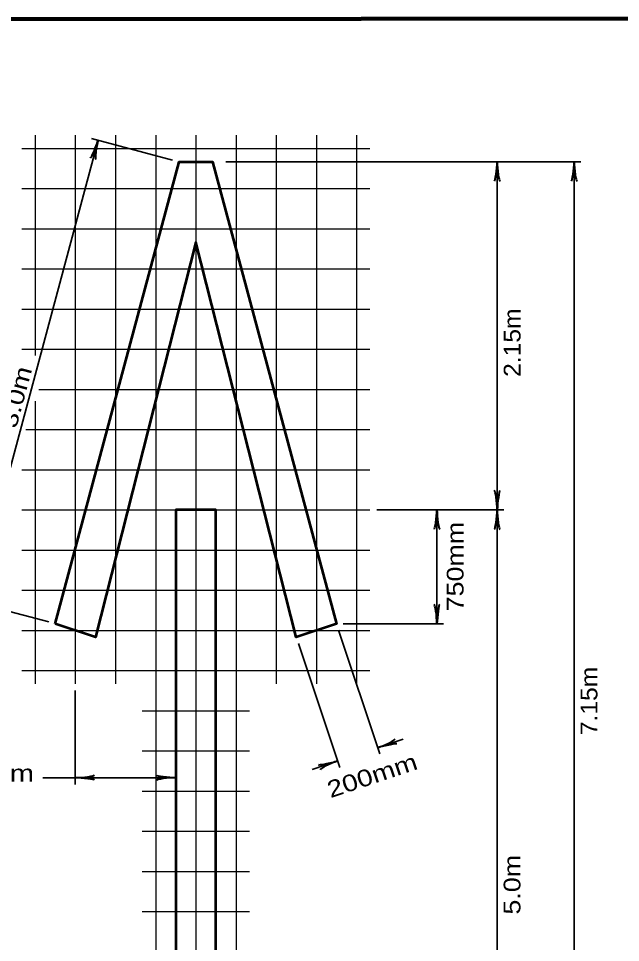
# Model space of a CAD drawing. Extents: x -96 to 617, y -65 to 388.
# Drawn here: x 230.8 to 320.7, y 245 to 383 of the extents above; entities that cross this region are included whole.
import ezdxf
from ezdxf.enums import TextEntityAlignment as Align

# ---------------------------------------------------------------- set-up
doc = ezdxf.new("R2010")
doc.units = 0
doc.layers.add('1', color=7, linetype='Continuous', lineweight=53)

msp = doc.modelspace()

# ---------------------------------------------------------------- linework, layer by layer
at = {"layer": '1', "lineweight": 35}
for p, q in [((242.716, 364.843), (224.216, 295.843)), ((253.852, 361.857), (241.75, 365.102)), ((261.818, 361.599), (314.818, 361.599)), ((302.318, 309.599), (302.318, 361.599)), ((313.818, 361.599), (313.818, 189.599)), ((284.318, 309.599), (303.318, 309.599)), ((293.318, 292.599), (293.318, 309.599)), ((302.318, 309.599), (302.318, 189.599)), ((235.352, 292.857), (223.25, 296.102)), ((278.634, 291.65), (284.804, 273.142)), ((279.318, 292.599), (294.318, 292.599)), ((272.634, 289.65), (278.804, 271.142)), ((239.318, 282.599), (239.318, 268.599)), ((284.487, 274.091), (288.282, 275.356)), ((274.693, 270.826), (278.487, 272.091)), ((234.476, 269.599), (254.318, 269.599))]:
    msp.add_line(p, q, dxfattribs=at)
at = {"layer": '1', "lineweight": 25}
for p, q in [((233.318, 365.599), (233.318, 332.682)), ((239.318, 365.599), (239.318, 283.599)), ((245.318, 365.599), (245.318, 283.599)), ((251.318, 365.599), (251.318, 181.599)), ((257.318, 365.599), (257.318, 181.599)), ((263.318, 365.599), (263.318, 181.599)), ((269.318, 365.599), (269.318, 283.599)), ((275.318, 365.599), (275.318, 283.599)), ((281.318, 365.599), (281.318, 283.599)), ((231.318, 363.599), (283.318, 363.599)), ((231.318, 357.599), (283.318, 357.599)), ((231.318, 351.599), (283.318, 351.599)), ((231.318, 345.599), (283.318, 345.599)), ((231.318, 339.599), (283.318, 339.599)), ((231.318, 333.599), (283.318, 333.599)), ((233.847, 327.599), (283.318, 327.599)), ((233.318, 325.866), (233.318, 283.599)), ((231.924, 321.599), (283.318, 321.599)), ((231.318, 315.599), (283.318, 315.599)), ((231.318, 309.599), (283.318, 309.599)), ((231.318, 303.599), (283.318, 303.599)), ((231.318, 297.599), (283.318, 297.599)), ((231.318, 291.599), (283.318, 291.599)), ((231.318, 285.599), (283.318, 285.599)), ((249.318, 279.599), (265.318, 279.599)), ((249.318, 273.599), (265.318, 273.599)), ((249.318, 267.599), (265.318, 267.599)), ((249.318, 261.599), (265.318, 261.599)), ((249.318, 255.599), (265.318, 255.599)), ((249.318, 249.599), (265.318, 249.599))]:
    msp.add_line(p, q, dxfattribs=at)
at = {"layer": '1', "lineweight": 158}
msp.add_lwpolyline([(611.853, 383.009), (-47.897, 382.926), (-47.814, -55.407)], dxfattribs=at)
at = {"layer": '1'}
for points in [[(236.318, 292.599), (254.818, 361.599), (259.818, 361.599), (278.318, 292.599), (272.318, 290.599), (257.318, 349.599), (242.318, 290.599)], [(260.318, 189.599), (260.318, 309.599), (254.318, 309.599), (254.318, 189.599)]]:
    msp.add_lwpolyline(points, close=True, dxfattribs=at)
at = {"layer": '1', "lineweight": 40}
for centre, major_axis, ratio, start_param, end_param in [((242.222, 363.816), (-0.625, -1.651), 0.07063, 6.2823074, 8.5597026), ((242.222, 363.816), (-0.625, -1.651), 0.07063, 6.2823074, 8.5597026), ((242.7, 363.718), (0.312, 1.765), 0.122415, 0.8963533, 3.1415927), ((242.7, 363.718), (0.312, 1.765), 0.122415, 0.8963533, 3.1415927), ((302.107, 360.478), (0.176, 1.756), 0.07063, 3.1407148, 5.41811), ((302.107, 360.478), (0.176, 1.756), 0.07063, 3.1407148, 5.41811), ((302.594, 360.507), (-0.156, 1.786), 0.122415, 0.8963533, 3.1415927), ((302.594, 360.507), (-0.156, 1.786), 0.122415, 0.8963533, 3.1415927), ((313.607, 360.478), (0.176, 1.756), 0.07063, 3.1407148, 5.41811), ((313.607, 360.478), (0.176, 1.756), 0.07063, 3.1407148, 5.41811), ((314.094, 360.507), (-0.156, 1.786), 0.122415, 0.8963533, 3.1415927), ((314.094, 360.507), (-0.156, 1.786), 0.122415, 0.8963533, 3.1415927), ((302.042, 310.69), (0.156, -1.786), 0.122415, 0.8963533, 3.1415927), ((302.042, 310.69), (0.156, -1.786), 0.122415, 0.8963533, 3.1415927), ((302.53, 310.719), (-0.176, -1.756), 0.07063, 3.1407148, 5.41811), ((302.53, 310.719), (-0.176, -1.756), 0.07063, 3.1407148, 5.41811), ((293.107, 308.478), (0.176, 1.756), 0.07063, 3.1407148, 5.41811), ((293.107, 308.478), (0.176, 1.756), 0.07063, 3.1407148, 5.41811), ((293.594, 308.507), (-0.156, 1.786), 0.122415, 0.8963533, 3.1415927), ((293.594, 308.507), (-0.156, 1.786), 0.122415, 0.8963533, 3.1415927), ((302.107, 308.478), (0.176, 1.756), 0.07063, 3.1407148, 5.41811), ((302.107, 308.478), (0.176, 1.756), 0.07063, 3.1407148, 5.41811), ((302.594, 308.507), (-0.156, 1.786), 0.122415, 0.8963533, 3.1415927), ((302.594, 308.507), (-0.156, 1.786), 0.122415, 0.8963533, 3.1415927), ((293.042, 293.69), (0.156, -1.786), 0.122415, 0.8963533, 3.1415927), ((293.042, 293.69), (0.156, -1.786), 0.122415, 0.8963533, 3.1415927), ((293.53, 293.719), (-0.176, -1.756), 0.07063, 3.1407148, 5.41811), ((293.53, 293.719), (-0.176, -1.756), 0.07063, 3.1407148, 5.41811), ((285.435, 274.698), (-1.645, -0.713), 0.122415, 0.8963533, 3.1415927), ((285.435, 274.698), (-1.645, -0.713), 0.122415, 0.8963533, 3.1415927), ((285.617, 274.244), (1.722, 0.389), 0.07063, 6.2823074, 8.5597026), ((285.617, 274.244), (1.722, 0.389), 0.07063, 6.2823074, 8.5597026), ((277.357, 271.937), (1.722, 0.389), 0.07063, 3.1407148, 5.41811), ((277.54, 271.484), (1.645, 0.713), 0.122415, 0.8963533, 3.1415927), ((240.409, 269.875), (-1.786, -0.156), 0.122415, 0.8963533, 3.1415927), ((240.409, 269.875), (-1.786, -0.156), 0.122415, 0.8963533, 3.1415927), ((240.439, 269.387), (-1.756, 0.176), 0.07063, 3.1407148, 5.41811), ((240.439, 269.387), (-1.756, 0.176), 0.07063, 3.1407148, 5.41811), ((253.227, 269.322), (1.786, 0.156), 0.122415, 0.8963533, 3.1415927), ((253.198, 269.81), (1.756, -0.176), 0.07063, 3.1407148, 5.41811)]:
    msp.add_ellipse(centre, major_axis=major_axis, ratio=ratio, start_param=start_param, end_param=end_param, dxfattribs=at)

# ---------------------------------------------------------------- texts
at = {"layer": '1'}
for s, rotation, width, p in [('2.15m', 90, 1.1, (305.8, 334.577)), ('3.0m', 74.991, 1.25, (231.684, 326.143)), ('750mm', 90, 1.2, (297.288, 301.126)), ('7.15m', 90, 1.1, (317.282, 281.056)), ('200mm', 18.435, 1.25, (284.03, 268.735)), ('5.0m', 90, 1.2, (305.784, 253.604))]:
    msp.add_text(s, height=2.5, rotation=rotation, dxfattribs=dict(at, width=width)).set_placement(p, align=Align.CENTER)
at = {"layer": '1', "width": 1.3}
msp.add_text('750 mm', height=2.5, dxfattribs=at).set_placement((225.294, 269.023), align=Align.CENTER)

doc.saveas('drawing.dxf')
